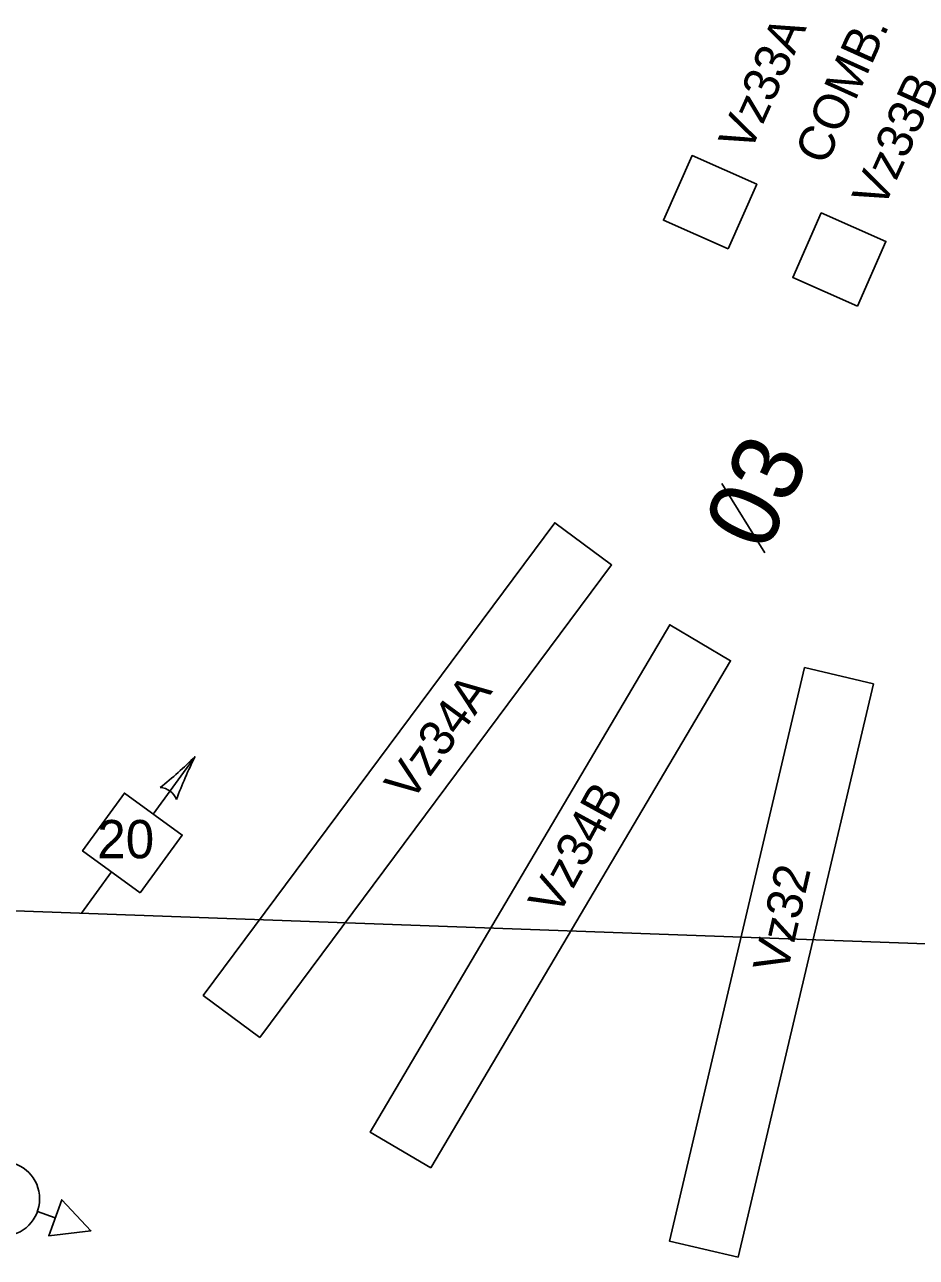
# Model space of a CAD drawing. Extents: x 647787 to 668496, y 640478 to 654412.
# Drawn here: x 661914.2 to 661989.9, y 647353.9 to 647458.5 of the extents above; entities that cross this region are included whole.
import ezdxf

# ---------------------------------------------------------------- set-up
doc = ezdxf.new("R2010")
doc.units = 0
for name, color, linetype in [('Default', 7, 'Continuous'), ('TEMP_DETECTION ZONE_Stage 2', 7, 'Continuous'), ('TEMP_SIGNAL_HEAD_STAGE 2', 7, 'Continuous'), ('TEMP_SIGNAL_HEAD_STAGE 3 SHILO', 7, 'Continuous'), ('TEMP_SIGNAL_POLES_STAGE 2', 7, 'Continuous'), ('TEXT_TEMP_SIGNAL_POLES_STAGE 2', 7, 'Continuous')]:
    doc.layers.add(name, color=color, linetype=linetype)

msp = doc.modelspace()

# ---------------------------------------------------------------- linework, layer by layer
at = {"layer": 'Default'}
msp.add_line((661973.38, 647419.54), (661977.01, 647413.65), dxfattribs=at)
at = {"layer": 'TEMP_DETECTION ZONE_Stage 2'}
for points in [[(661973.9, 647439.46), (661968.41, 647441.89), (661970.84, 647447.37), (661976.33, 647444.94)], [(661984.87, 647434.6), (661979.38, 647437.03), (661981.81, 647442.51), (661987.3, 647440.09)], [(661934.16, 647372.52), (661929.35, 647376.1), (661959.19, 647416.22), (661964.01, 647412.63)], [(661948.67, 647361.46), (661943.51, 647364.51), (661968.95, 647407.56), (661974.11, 647404.5)], [(661974.76, 647353.88), (661968.92, 647355.25), (661980.39, 647403.92), (661986.23, 647402.54)]]:
    msp.add_lwpolyline(points, close=True, dxfattribs=at)
at = {"layer": 'TEMP_SIGNAL_HEAD_STAGE 2'}
for p, q in [((661925.11, 647391.49), (661928.66, 647396.38)), ((661919, 647383.07), (661921.55, 647386.58))]:
    msp.add_line(p, q, dxfattribs=at)
msp.add_lwpolyline([(661924, 647384.8), (661919.1, 647388.36), (661922.66, 647393.27), (661927.57, 647389.71)], close=True, dxfattribs=at)
for centre, radius, start, end in [((661907.67, 647417.07), 29.47, 307.6752, 315.4133), ((661954.84, 647382.83), 29.47, 152.6299, 160.368), ((661925.57, 647392.12), 1.63, 22.1743, 85.8689)]:
    msp.add_arc(centre, radius, start, end, dxfattribs=at)
at = {"layer": 'TEMP_SIGNAL_HEAD_STAGE 3 SHILO'}
for points in [[(661916.23, 647355.71), (661917.34, 647358.76), (661919.81, 647356.13), (661916.23, 647355.71)], [(661916.23, 647355.71), (661917.34, 647358.76), (661919.81, 647356.13), (661916.23, 647355.71)], [(661915.28, 647357.78), (661916.78, 647357.24)], [(661915.28, 647357.78), (661916.78, 647357.24)]]:
    msp.add_lwpolyline(points, dxfattribs=at)
msp.add_lwpolyline([(661919.81, 647356.13), (661917.34, 647358.76), (661916.23, 647355.71)], close=True, dxfattribs=at)
msp.add_lwpolyline([(661919.81, 647356.13), (661917.34, 647358.76), (661916.23, 647355.71)], close=True, dxfattribs=at)
msp.add_circle((661912.29, 647358.84), 3.17, dxfattribs=at)
msp.add_circle((661912.29, 647358.84), 3.17, dxfattribs=at)
at = {"layer": 'TEMP_SIGNAL_POLES_STAGE 2'}
msp.add_line((662012.45, 647379.68), (661894.7, 647383.95), dxfattribs=at)

# ---------------------------------------------------------------- texts
at = {"layer": 'Default'}
msp.add_text('03', height=6, rotation=65.2141, dxfattribs=at).set_placement((661977.12, 647413.55))
at = {"layer": 'TEMP_DETECTION ZONE_Stage 2'}
for s, rotation, p in [('Vz33A', 65.6969, (661975.73, 647447.49)), ('COMB.', 65.6969, (661982.2, 647446.44)), ('Vz33B', 65.6969, (661987.06, 647442.72)), ('Vz34A', 53.7229, (661946.97, 647392.4)), ('Vz34B', 61.3617, (661959.44, 647382.7)), ('Vz32', 77.15, (661978.9, 647377.86))]:
    msp.add_text(s, height=3, rotation=rotation, dxfattribs=at).set_placement(p)
at = {"layer": 'TEXT_TEMP_SIGNAL_POLES_STAGE 2'}
msp.add_text('20', height=3.25, dxfattribs=at).set_placement((661920.35, 647387.74))

doc.saveas('drawing.dxf')
